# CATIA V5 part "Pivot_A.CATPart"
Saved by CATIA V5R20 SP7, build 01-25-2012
Part number: Pivot_A
Bounding box of the stored display mesh (mm): x 72.5 to 77.5, y 27.5 to 32.5, z -6 to 6
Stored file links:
  D:\IFMA\COURS\2A\projet balance IAO\catia\Pivot_A.CATPart
  D:\IFMA\COURS\2A\projet balance IAO\catia\Ass_projet_balance.CATProduct
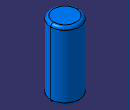
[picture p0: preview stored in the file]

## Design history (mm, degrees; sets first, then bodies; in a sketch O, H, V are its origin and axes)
Set1
  Plane1 "Plan.KDAF": linked copy from another document
  Point1 "Point.A": linked copy from another document
Body1 (main body)
  Sketch1 on Plane1, origin (0, 0, 0), H (1, 0, 0), V (0, 1, 0)
    circle A1 centre (75, 30) radius 2.5
    point P1 (75, 30)
    reference projected point E1 (75, 30) from Point1
    radius A1 = 2.5
    coincidence: P1 E1
  Pad1: profile Sketch1, direction (0, 0, 1), length 6, mirrored extent
  Fillet1: radius 0.5, on edge [face of Pad1 from Sketch1.A1 | end face of Pad1]; edge [start face of Pad1 | face of Pad1 from Sketch1.A1]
